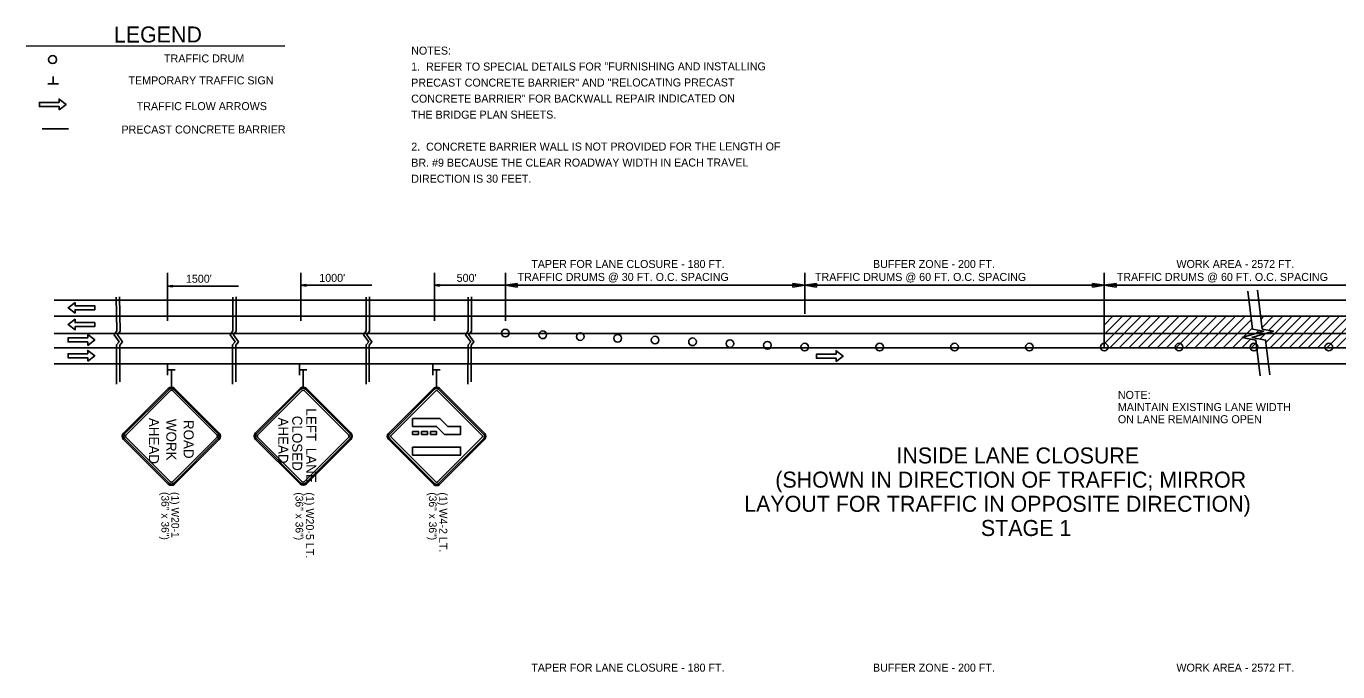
# Model space of a CAD drawing. Extents: x 1930579 to 1937984, y 596452 to 597630.
# Drawn here: x 1936432 to 1937415, y 597133 to 597617 of the extents above; entities that cross this region are included whole.
import ezdxf

# ---------------------------------------------------------------- set-up
doc = ezdxf.new("R2010")
doc.units = 0
for name, color, linetype in [('B_StampSCR', 7, 'Continuous'), ('Default', 7, 'Continuous'), ('P_TC_Signs_Permanent', 7, 'Continuous'), ('P_TC_Signs_Temporary', 7, 'Continuous'), ('R_Border', 7, 'Continuous'), ('R_MOT', 7, 'Continuous'), ('R_Striping', 7, 'Continuous')]:
    doc.layers.add(name, color=color, linetype=linetype)

msp = doc.modelspace()

# ---------------------------------------------------------------- linework, layer by layer
at = {"layer": 'B_StampSCR'}
msp.add_line((1937804.86, 597386.36), (1936452.69, 597386.36), dxfattribs=at)
at = {"layer": 'Default'}
for p, q in [((1936463.36, 597539.67), (1936443.86, 597539.67)), ((1936537.79, 597431.71), (1936537.79, 597395.8)), ((1936637.79, 597431.71), (1936637.79, 597395.8)), ((1936737.79, 597431.71), (1936737.79, 597395.8)), ((1936791.02, 597431.71), (1936791.02, 597395.8)), ((1937015.53, 597431.71), (1937015.53, 597400.99)), ((1937240.04, 597431.71), (1937240.04, 597375.6)), ((1936541.62, 597422.3), (1936537.79, 597421.72)), ((1936537.79, 597421.72), (1936591.02, 597421.72)), ((1936541.62, 597421.15), (1936537.79, 597421.72)), ((1936541.62, 597422.2), (1936538.43, 597421.72)), ((1936541.62, 597421.24), (1936538.43, 597421.72)), ((1936541.62, 597422.1), (1936539.09, 597421.72)), ((1936541.62, 597421.34), (1936539.09, 597421.72)), ((1936541.62, 597422.01), (1936539.73, 597421.72)), ((1936541.62, 597421.44), (1936539.73, 597421.72)), ((1936541.62, 597421.91), (1936540.37, 597421.72)), ((1936541.62, 597421.54), (1936540.37, 597421.72)), ((1936541.62, 597421.81), (1936541.01, 597421.72)), ((1936541.62, 597421.63), (1936541.01, 597421.72)), ((1936541.62, 597421.15), (1936541.62, 597422.3)), ((1936641.62, 597422.98), (1936637.79, 597422.4)), ((1936637.79, 597422.4), (1936691.02, 597422.4)), ((1936641.62, 597421.83), (1936637.79, 597422.4)), ((1936641.62, 597422.88), (1936638.43, 597422.4)), ((1936641.62, 597421.92), (1936638.43, 597422.4)), ((1936641.62, 597422.78), (1936639.09, 597422.4)), ((1936641.62, 597422.02), (1936639.09, 597422.4)), ((1936641.62, 597422.69), (1936639.73, 597422.4)), ((1936641.62, 597422.12), (1936639.73, 597422.4)), ((1936641.62, 597422.59), (1936640.37, 597422.4)), ((1936641.62, 597422.22), (1936640.37, 597422.4)), ((1936641.62, 597422.49), (1936641.01, 597422.4)), ((1936641.62, 597422.31), (1936641.01, 597422.4)), ((1936641.62, 597421.83), (1936641.62, 597422.98)), ((1936741.62, 597422.98), (1936737.79, 597422.4)), ((1936737.79, 597422.4), (1936791.02, 597422.4)), ((1936741.62, 597421.83), (1936737.79, 597422.4)), ((1936741.62, 597422.88), (1936738.43, 597422.4)), ((1936741.62, 597421.92), (1936738.43, 597422.4)), ((1936741.62, 597422.78), (1936739.09, 597422.4)), ((1936741.62, 597422.02), (1936739.09, 597422.4)), ((1936741.62, 597422.69), (1936739.73, 597422.4)), ((1936741.62, 597422.12), (1936739.73, 597422.4)), ((1936741.62, 597422.59), (1936740.37, 597422.4)), ((1936741.62, 597422.22), (1936740.37, 597422.4)), ((1936741.62, 597422.49), (1936741.01, 597422.4)), ((1936741.62, 597422.31), (1936741.01, 597422.4)), ((1936741.62, 597421.83), (1936741.62, 597422.98)), ((1936791.02, 597422.4), (1936799.89, 597423.73)), ((1937015.53, 597422.4), (1936791.02, 597422.4)), ((1936799.89, 597421.07), (1936791.02, 597422.4)), ((1936799.89, 597423.73), (1936799.89, 597421.07)), ((1937015.53, 597422.4), (1937006.66, 597423.73)), ((1937006.66, 597423.73), (1937006.66, 597421.07)), ((1937006.66, 597421.07), (1937015.53, 597422.4)), ((1937015.53, 597422.4), (1937024.4, 597423.73)), ((1937240.04, 597422.4), (1937015.53, 597422.4)), ((1937024.4, 597421.07), (1937015.53, 597422.4)), ((1937024.4, 597423.73), (1937024.4, 597421.07)), ((1937231.17, 597421.07), (1937231.17, 597423.73)), ((1937231.17, 597423.73), (1937240.04, 597422.4)), ((1937240.04, 597422.4), (1937231.17, 597421.07)), ((1937248.9, 597423.73), (1937240.04, 597422.4)), ((1937464.54, 597422.4), (1937240.04, 597422.4)), ((1937240.04, 597422.4), (1937248.9, 597421.07)), ((1937248.9, 597421.07), (1937248.9, 597423.73)), ((1937804.86, 597411.17), (1936452.69, 597411.17)), ((1937804.86, 597399.17), (1936452.69, 597399.17)), ((1937804.86, 597399.17), (1936452.69, 597399.17)), ((1937240.04, 597392.61), (1937246.6, 597399.17)), ((1937240.05, 597385.55), (1937253.67, 597399.17)), ((1937240.22, 597378.65), (1937260.74, 597399.17)), ((1937244.24, 597375.6), (1937267.81, 597399.17)), ((1937251.31, 597375.6), (1937274.88, 597399.17)), ((1937258.39, 597375.6), (1937281.95, 597399.17)), ((1937265.46, 597375.6), (1937289.02, 597399.17)), ((1937272.53, 597375.6), (1937296.09, 597399.17)), ((1937279.6, 597375.6), (1937303.17, 597399.17)), ((1937286.67, 597375.6), (1937310.24, 597399.17)), ((1937293.74, 597375.6), (1937317.31, 597399.17)), ((1937300.81, 597375.6), (1937324.38, 597399.17)), ((1937307.88, 597375.6), (1937331.45, 597399.17)), ((1937314.95, 597375.6), (1937338.52, 597399.17)), ((1937322.03, 597375.6), (1937345.59, 597399.17)), ((1937329.1, 597375.6), (1937350.36, 597396.87)), ((1937357.62, 597397.06), (1937359.73, 597399.17)), ((1937357.62, 597397.06), (1937359.73, 597399.17)), ((1937358.41, 597390.77), (1937366.81, 597399.17)), ((1937361.21, 597379.43), (1937380.95, 597399.17)), ((1937363.4, 597388.69), (1937373.88, 597399.17)), ((1937364.45, 597375.6), (1937388.02, 597399.17)), ((1937371.52, 597375.6), (1937395.09, 597399.17)), ((1937378.59, 597375.6), (1937402.16, 597399.17)), ((1937385.67, 597375.6), (1937409.23, 597399.17)), ((1937392.74, 597375.6), (1937416.3, 597399.17)), ((1937399.81, 597375.6), (1937423.37, 597399.17)), ((1937406.88, 597375.6), (1937430.45, 597399.17)), ((1937413.95, 597375.6), (1937437.52, 597399.17)), ((1937336.17, 597375.6), (1937351.15, 597390.58)), ((1937354.06, 597386.43), (1937356.29, 597388.66)), ((1937343.24, 597375.6), (1937349.69, 597382.05)), ((1937350.31, 597375.6), (1937353.95, 597379.24)), ((1937350.85, 597383.22), (1937350.89, 597383.26)), ((1937356.79, 597382.08), (1937361.04, 597386.33)), ((1937804.86, 597375.6), (1936452.69, 597375.6)), ((1937804.86, 597363.6), (1936452.69, 597363.6)), ((1936537.79, 597355), (1936537.79, 597362.98)), ((1936537.91, 597358.97), (1936543.36, 597358.97)), ((1936636.62, 597354.95), (1936636.62, 597362.93)), ((1936636.74, 597358.92), (1936642.18, 597358.92)), ((1936736.62, 597354.95), (1936736.62, 597362.93)), ((1936736.74, 597358.92), (1936742.18, 597358.92))]:
    msp.add_line(p, q, dxfattribs=at)
for points in [[(1937347.74, 597417.86), (1937351.28, 597389.54), (1937359.53, 597388.09), (1937343.51, 597383.23), (1937353.71, 597381.28), (1937356.93, 597354.52)], [(1937354.91, 597418.76), (1937358.56, 597389.54), (1937366.82, 597388.09), (1937350.79, 597383.23), (1937360.99, 597381.28), (1937364.11, 597355.38)], [(1936499.33, 597413.45), (1936499.72, 597388.21), (1936497.77, 597385.31), (1936501.57, 597380.12), (1936499.57, 597377.72), (1936499.56, 597348.37)], [(1936501.73, 597413.68), (1936502.12, 597388.11), (1936500.17, 597385.21), (1936503.96, 597380.02), (1936501.96, 597377.62), (1936501.96, 597350.06)], [(1936586.69, 597413.45), (1936586.69, 597388.21), (1936584.74, 597385.31), (1936588.54, 597380.12), (1936586.54, 597377.72), (1936586.54, 597348.37)], [(1936589.09, 597413.68), (1936589.09, 597388.11), (1936587.14, 597385.21), (1936590.94, 597380.02), (1936588.94, 597377.62), (1936588.94, 597350.06)], [(1936686.69, 597413.45), (1936686.69, 597388.21), (1936684.74, 597385.31), (1936688.54, 597380.12), (1936686.54, 597377.72), (1936686.54, 597348.37)], [(1936689.09, 597413.68), (1936689.09, 597388.11), (1936687.14, 597385.21), (1936690.94, 597380.02), (1936688.94, 597377.62), (1936688.94, 597350.06)], [(1936763.16, 597413.45), (1936763.16, 597388.21), (1936761.21, 597385.31), (1936765.01, 597380.12), (1936763.01, 597377.72), (1936763, 597348.37)], [(1936765.56, 597413.68), (1936765.56, 597388.11), (1936763.61, 597385.21), (1936767.4, 597380.02), (1936765.41, 597377.62), (1936765.4, 597350.06)]]:
    msp.add_lwpolyline(points, dxfattribs=at)
for centre, radius in [((1936451.57, 597591.57), 3), ((1936791.02, 597386.59), 2.87), ((1936819.09, 597385.28), 2.87), ((1936847.15, 597383.97), 2.87), ((1936875.21, 597382.65), 2.87), ((1936903.28, 597381.34), 2.87), ((1936931.34, 597380.03), 2.87), ((1936959.4, 597378.71), 2.87), ((1936987.47, 597377.4), 2.87), ((1937015.53, 597376.09), 2.87), ((1937071.66, 597376.09), 2.87), ((1937127.78, 597376.09), 2.87), ((1937183.91, 597376.09), 2.87), ((1937240.04, 597376.09), 2.87), ((1937296.16, 597376.09), 2.87), ((1937352.29, 597376.09), 2.87), ((1937408.42, 597376.09), 2.87)]:
    msp.add_circle(centre, radius, dxfattribs=at)
at = {"layer": 'P_TC_Signs_Permanent'}
for p, q in [((1936737.34, 597345.24), (1936703.4, 597311.3)), ((1936775.52, 597311.3), (1936741.58, 597345.24)), ((1936703.4, 597307.05), (1936737.34, 597273.11)), ((1936757.46, 597301.13), (1936757.46, 597295.13))]:
    msp.add_line(p, q, dxfattribs=at)
for points in [[(1936704.03, 597310.66), (1936737.97, 597344.6)], [(1936739.04, 597343.54), (1936705.09, 597309.6)], [(1936773.82, 597309.6), (1936739.88, 597343.54)], [(1936740.94, 597344.6), (1936774.89, 597310.66)], [(1936705.09, 597308.75), (1936739.04, 597274.81)], [(1936739.88, 597274.81), (1936773.82, 597308.75)], [(1936737.97, 597273.75), (1936704.03, 597307.69)], [(1936774.89, 597307.69), (1936740.94, 597273.75)], [(1936741.58, 597273.11), (1936758.55, 597290.08), (1936775.52, 597307.05)]]:
    msp.add_lwpolyline(points, dxfattribs=at)
for points in [[(1936721.46, 597322.67), (1936721.46, 597316.67), (1936739.46, 597316.67), (1936745.46, 597310.67), (1936757.46, 597310.67), (1936757.46, 597316.67), (1936747.94, 597316.67), (1936741.94, 597322.67)], [(1936721.46, 597312.77), (1936721.46, 597310.67), (1936725.96, 597310.67), (1936725.96, 597312.77)], [(1936728.21, 597312.77), (1936728.21, 597310.67), (1936732.71, 597310.67), (1936732.71, 597312.77)], [(1936734.96, 597312.77), (1936734.96, 597310.67), (1936739.46, 597310.67), (1936739.46, 597312.77)], [(1936721.46, 597301.13), (1936721.46, 597295.13), (1936757.46, 597295.13), (1936757.46, 597301.13)]]:
    msp.add_lwpolyline(points, close=True, dxfattribs=at)
for centre, radius, start, end in [((1936739.46, 597343.12), 3, 45, 135), ((1936739.46, 597343.12), 2.1, 45, 135), ((1936739.46, 597343.12), 0.6, 45, 135), ((1936705.52, 597309.17), 3, 135, 225), ((1936705.52, 597309.17), 2.1, 135, 225), ((1936705.52, 597309.17), 0.6, 135, 225), ((1936773.4, 597309.17), 0.6, 315, 45), ((1936773.4, 597309.17), 2.1, 315, 45), ((1936773.4, 597309.17), 3, 315, 45), ((1936739.46, 597275.23), 3, 225, 315), ((1936739.46, 597275.23), 2.1, 225, 315), ((1936739.46, 597275.23), 0.6, 225, 315)]:
    msp.add_arc(centre, radius, start, end, dxfattribs=at)
at = {"layer": 'P_TC_Signs_Temporary'}
for p, q in [((1936504.84, 597311.64), (1936538.25, 597345.05)), ((1936505.5, 597310.98), (1936538.91, 597344.39)), ((1936506.43, 597310.05), (1936539.84, 597343.46)), ((1936541.43, 597343.46), (1936574.84, 597310.05)), ((1936542.36, 597344.39), (1936575.77, 597310.98)), ((1936543.02, 597345.05), (1936576.43, 597311.64)), ((1936603.66, 597311.72), (1936637.07, 597345.13)), ((1936604.33, 597311.05), (1936637.74, 597344.46)), ((1936605.25, 597310.13), (1936638.66, 597343.54)), ((1936640.26, 597343.54), (1936673.67, 597310.13)), ((1936641.18, 597344.46), (1936674.59, 597311.05)), ((1936641.85, 597345.13), (1936675.26, 597311.72)), ((1936539.84, 597275.05), (1936506.43, 597308.46)), ((1936574.84, 597308.46), (1936541.43, 597275.05)), ((1936638.66, 597275.12), (1936605.25, 597308.53)), ((1936673.67, 597308.53), (1936640.26, 597275.12)), ((1936538.25, 597273.46), (1936504.84, 597306.87)), ((1936538.91, 597274.12), (1936505.5, 597307.53)), ((1936575.77, 597307.53), (1936542.36, 597274.12)), ((1936576.43, 597306.87), (1936543.02, 597273.46)), ((1936637.07, 597273.53), (1936603.66, 597306.94)), ((1936637.74, 597274.2), (1936604.33, 597307.61)), ((1936674.59, 597307.61), (1936641.18, 597274.2)), ((1936675.26, 597306.94), (1936641.85, 597273.53))]:
    msp.add_line(p, q, dxfattribs=at)
for centre, radius, start, end in [((1936540.63, 597342.67), 3.38, 45, 135), ((1936540.63, 597342.67), 2.44, 45, 135), ((1936540.63, 597342.67), 1.12, 45, 135), ((1936639.46, 597342.74), 3.38, 45, 135), ((1936639.46, 597342.74), 2.44, 45, 135), ((1936639.46, 597342.74), 1.12, 45, 135), ((1936507.22, 597309.26), 3.38, 135, 225), ((1936507.22, 597309.26), 2.44, 135, 225), ((1936507.22, 597309.26), 1.13, 135, 225), ((1936574.04, 597309.26), 1.13, 315, 45), ((1936574.04, 597309.26), 2.44, 315, 45), ((1936574.04, 597309.26), 3.38, 315, 45), ((1936606.05, 597309.33), 3.38, 135, 225), ((1936606.05, 597309.33), 2.44, 135, 225), ((1936606.05, 597309.33), 1.13, 135, 225), ((1936672.87, 597309.33), 1.13, 315, 45), ((1936672.87, 597309.33), 2.44, 315, 45), ((1936672.87, 597309.33), 3.38, 315, 45), ((1936540.63, 597275.85), 3.38, 225, 315), ((1936540.63, 597275.85), 2.44, 225, 315), ((1936540.63, 597275.85), 1.12, 225, 315), ((1936639.46, 597275.92), 3.38, 225, 315), ((1936639.46, 597275.92), 2.44, 225, 315), ((1936639.46, 597275.92), 1.12, 225, 315)]:
    msp.add_arc(centre, radius, start, end, dxfattribs=at)
at = {"layer": 'R_Border'}
for p, q in [((1936431.79, 597601.6), (1936625.71, 597601.73)), ((1936451.95, 597573.4), (1936451.95, 597578.86)), ((1936455.93, 597573.29), (1936447.93, 597573.28)), ((1936540.63, 597358.97), (1936540.63, 597346.04)), ((1936639.46, 597358.91), (1936639.46, 597346.12)), ((1936739.46, 597358.91), (1936739.46, 597346.12))]:
    msp.add_line(p, q, dxfattribs=at)
at = {"layer": 'R_MOT'}
msp.add_lwpolyline([(1936456.44, 597553.89), (1936461.63, 597557.89), (1936456.44, 597561.89), (1936456.44, 597559.39), (1936441.73, 597559.38), (1936441.73, 597556.38), (1936456.44, 597556.39)], close=True, dxfattribs=at)
at = {"layer": 'R_Striping'}
for points in [[(1936468.42, 597409.53), (1936463.23, 597405.53), (1936468.42, 597401.53), (1936468.42, 597404.03), (1936483.13, 597404.03), (1936483.13, 597407.03), (1936468.42, 597407.03)], [(1936468.42, 597396.9), (1936463.23, 597392.9), (1936468.42, 597388.9), (1936468.42, 597391.4), (1936483.13, 597391.4), (1936483.13, 597394.4), (1936468.42, 597394.4)], [(1936477.94, 597377.39), (1936483.13, 597381.39), (1936477.94, 597385.39), (1936477.94, 597382.89), (1936463.23, 597382.89), (1936463.23, 597379.89), (1936477.94, 597379.89)], [(1936477.94, 597365.61), (1936483.13, 597369.61), (1936477.94, 597373.61), (1936477.94, 597371.11), (1936463.23, 597371.11), (1936463.23, 597368.11), (1936477.94, 597368.11)], [(1937038.98, 597365.27), (1937044.17, 597369.27), (1937038.98, 597373.27), (1937038.98, 597370.77), (1937024.27, 597370.77), (1937024.27, 597367.77), (1937038.98, 597367.77)]]:
    msp.add_lwpolyline(points, close=True, dxfattribs=at)

# ---------------------------------------------------------------- texts
at = {"layer": 'Default'}
for s, height, p in [('TAPER FOR LANE CLOSURE - 180 FT.', 6, (1936810.44, 597435.36)), ('BUFFER ZONE - 200 FT.', 6, (1937066.66, 597435.36)), ('WORK AREA - 2572 FT. ', 6, (1937294.16, 597435.36)), ("1500'", 6, (1936551.51, 597424.3)), ("1000'", 6, (1936651.51, 597424.96)), ("500'", 6, (1936754.51, 597424.96)), ('TRAFFIC DRUMS @ 30 FT. O.C. SPACING', 6, (1936800.17, 597425.65)), ('TRAFFIC DRUMS @ 60 FT. O.C. SPACING', 6, (1937023.16, 597425.65)), ('TRAFFIC DRUMS @ 60 FT. O.C. SPACING', 6, (1937249.43, 597425.65)), ('INSIDE LANE CLOSURE', 12, (1937084.26, 597288.86)), ('(SHOWN IN DIRECTION OF TRAFFIC; MIRROR', 12, (1936993.41, 597270.74)), (' LAYOUT FOR TRAFFIC IN OPPOSITE DIRECTION)', 12, (1936965.63, 597252.62)), ('STAGE 1', 12, (1937147.56, 597234.5)), ('TAPER FOR LANE CLOSURE - 180 FT.', 6, (1936810.44, 597132.84)), ('BUFFER ZONE - 200 FT.', 6, (1937066.66, 597132.84)), ('WORK AREA - 2572 FT. ', 6, (1937294.16, 597132.84))]:
    msp.add_text(s, height=height, rotation=360, dxfattribs=at).set_placement(p)
at = {"layer": 'P_TC_Signs_Temporary'}
for s, p in [('LEFT\u2002LANE', (1936641.71, 597330.13)), (' AHEAD ', (1936523.8, 597325.8)), ('WORK', (1936536.82, 597322.25)), (' ROAD ', (1936549.85, 597324.28)), (' AHEAD ', (1936620.71, 597326.1)), ('CLOSED', (1936631.21, 597324.58))]:
    msp.add_text(s, height=7.5, rotation=270, dxfattribs=at).set_placement(p)
at = {"layer": 'R_Border'}
for s, height, rotation, p in [('LEGEND', 12, 0.03878, (1936497.52, 597604.33)), ('TRAFFIC DRUM', 6, 0.03876, (1936535.11, 597589.37)), ('NOTES:', 6, 0.03876, (1936720.4, 597595.26)), ('1.  REFER TO SPECIAL DETAILS FOR "FURNISHING AND INSTALLING', 6, 0.03876, (1936720.41, 597583.26)), ('TEMPORARY TRAFFIC SIGN', 6, 0.03876, (1936508.44, 597572.89)), ('PRECAST CONCRETE BARRIER" AND "RELOCATING PRECAST', 6, 0.03876, (1936720.42, 597571.26)), ('CONCRETE BARRIER" FOR BACKWALL REPAIR INDICATED ON', 6, 0.03876, (1936720.43, 597559.26)), ('TRAFFIC FLOW ARROWS', 6, 0.03876, (1936514.64, 597553.61)), ('THE BRIDGE PLAN SHEETS.  ', 6, 0.03876, (1936720.43, 597547.26)), ('PRECAST CONCRETE BARRIER', 6, 0.03876, (1936503.2, 597536.1)), ('2.  CONCRETE BARRIER WALL IS NOT PROVIDED FOR THE LENGTH OF ', 6, 0.03876, (1936720.45, 597523.26)), ('BR. #9 BECAUSE THE CLEAR ROADWAY WIDTH IN EACH TRAVEL', 6, 0.03876, (1936720.46, 597511.26)), ('DIRECTION IS 30 FEET.', 6, 0.03876, (1936720.47, 597499.26)), ('NOTE:', 6, 360, (1937250.26, 597337.23)), ('MAINTAIN EXISTING LANE WIDTH', 6, 360, (1937250.26, 597328.12)), ('ON LANE REMAINING OPEN', 6, 360, (1937250.26, 597319.01)), ('(36" x 36")', 5.76, 270, (1936533.14, 597267.47)), ('(1) W20-1', 5.76, 270, (1936540.63, 597267.47)), ('(36" x 36")', 5.76, 270, (1936633.7, 597267.23)), ('(1) W20-5 LT.', 6, 270, (1936641.47, 597267.23)), ('(36" x 36")', 5.76, 270, (1936733.7, 597267.23)), ('(1) W4-2 LT.', 6, 270, (1936741.47, 597267.23))]:
    msp.add_text(s, height=height, rotation=rotation, dxfattribs=at).set_placement(p)

doc.saveas('drawing.dxf')
